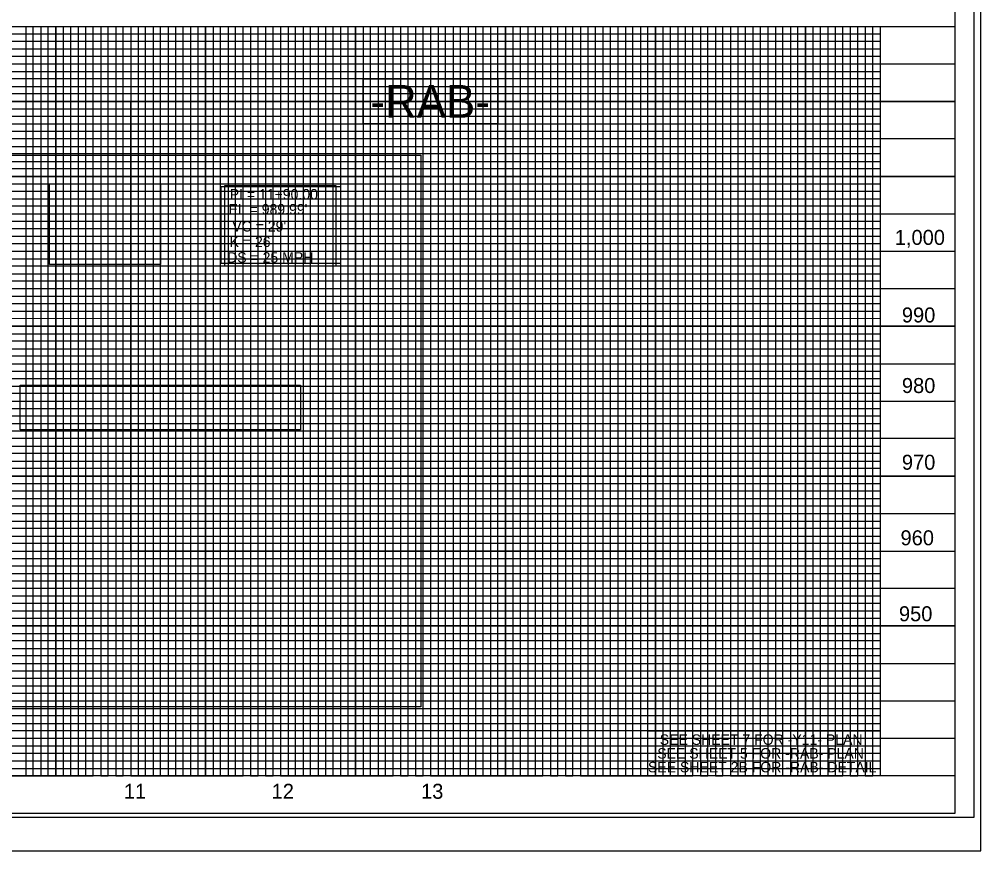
# Model space of a CAD drawing. Extents: x 1628636 to 1631253, y 896159 to 897520.
# Drawn here: x 1630102 to 1630743, y 896159 to 896714 of the extents above; entities that cross this region are included whole.
import ezdxf

# ---------------------------------------------------------------- set-up
doc = ezdxf.new("R2010")
doc.units = 0
for name, color, linetype in [('Prop DSN Text', 7, 'Continuous'), ('Prop PHM Black Shape', 7, 'Continuous'), ('Prop Vertical Profile Curve Label', 7, 'Continuous'), ('Prop VPI Label', 7, 'Continuous'), ('Scratch_Level_6', 7, 'Continuous'), ('Sheet Cutting Line CELL', 7, 'Continuous'), ('Sheet DOT Grid CELL', 7, 'Continuous'), ('Sheet Layout Profile Border Port 2', 7, 'Continuous'), ('Sheet Plot Border Inside CELL', 7, 'Continuous'), ('Sheet Plot Border Outside CELL', 7, 'Continuous'), ('Sheet Profile CELL', 7, 'Continuous'), ('Sheet Profile Grid Major CELL', 7, 'Continuous'), ('Sheet Profile Grid Middle CELL', 7, 'Continuous'), ('Sheet Profile Grid Minor CELL', 7, 'Continuous')]:
    doc.layers.add(name, color=color, linetype=linetype)

msp = doc.modelspace()

# ---------------------------------------------------------------- linework, layer by layer
at = {"layer": 'Prop PHM Black Shape'}
for points in [[(1630331.5, 896673.9), (1630421.5, 896673.9), (1630421.5, 896643.9), (1630331.5, 896643.9)], [(1630122.44, 896603.99), (1630196.49, 896603.99), (1630196.49, 896550.11), (1630122.44, 896550.11)], [(1630236.81, 896602.21), (1630316.54, 896602.21), (1630316.54, 896550.85), (1630236.81, 896550.85)], [(1630239.35, 896602.77), (1630313.4, 896602.77), (1630313.4, 896548.89), (1630239.35, 896548.89)], [(1630102.84, 896469.52), (1630289.81, 896469.52), (1630289.81, 896439.73), (1630102.84, 896439.73)], [(1630521.5, 896238.9), (1630676.5, 896238.9), (1630676.5, 896208.9), (1630521.5, 896208.9)]]:
    msp.add_lwpolyline(points, close=True, dxfattribs=at)
at = {"layer": 'Scratch_Level_6'}
for points in [[(1630176.5, 896658.9), (1630576.5, 896658.9), (1630576.5, 896358.9), (1630176.5, 896358.9)], [(1630068.19, 896623), (1630370.03, 896623), (1630370.03, 896254.89), (1630068.19, 896254.89)]]:
    msp.add_lwpolyline(points, close=True, dxfattribs=at)
at = {"layer": 'Sheet Cutting Line CELL'}
msp.add_line((1629059.5, 896158.9), (1630743.5, 896158.9), dxfattribs=at)
at = {"layer": 'Sheet DOT Grid CELL'}
for p, q in [((1629226.5, 896708.9), (1630726.39, 896708.9)), ((1630126.5, 896708.9), (1630126.5, 896208.9)), ((1630176.5, 896708.9), (1630176.5, 896208.9)), ((1630226.5, 896708.9), (1630226.5, 896208.9)), ((1630276.5, 896708.9), (1630276.5, 896208.9)), ((1630326.5, 896708.9), (1630326.5, 896208.9)), ((1630376.5, 896708.9), (1630376.5, 896208.9)), ((1630426.5, 896708.9), (1630426.5, 896208.9)), ((1630476.5, 896708.9), (1630476.5, 896208.9)), ((1630526.5, 896708.9), (1630526.5, 896208.9)), ((1630576.5, 896708.9), (1630576.5, 896208.9)), ((1630626.5, 896708.9), (1630626.5, 896208.9)), ((1630676.5, 896708.9), (1630676.5, 896208.9)), ((1629226.5, 896658.9), (1630726.39, 896658.9)), ((1629226.5, 896608.9), (1630726.39, 896608.9)), ((1629226.5, 896558.9), (1630726.39, 896558.9)), ((1629226.5, 896508.9), (1630726.39, 896508.9)), ((1629226.5, 896458.9), (1630726.39, 896458.9)), ((1629226.5, 896408.9), (1630726.39, 896408.9)), ((1629226.5, 896358.9), (1630726.39, 896358.9)), ((1629226.5, 896308.9), (1630726.39, 896308.9)), ((1629226.5, 896258.9), (1630726.39, 896258.9))]:
    msp.add_line(p, q, dxfattribs=at)
at = {"layer": 'Sheet Layout Profile Border Port 2'}
msp.add_lwpolyline([(1629276.5, 896708.9), (1630676.5, 896708.9), (1630676.5, 896208.9), (1629276.5, 896208.9)], close=True, dxfattribs=at)
at = {"layer": 'Sheet Plot Border Inside CELL'}
msp.add_lwpolyline([(1629072.5, 896181.35), (1630739, 896181.35), (1630739, 897236.45), (1629072.5, 897236.45)], close=True, dxfattribs=at)
at = {"layer": 'Sheet Plot Border Outside CELL'}
msp.add_lwpolyline([(1629059.5, 896158.9), (1630743.5, 896158.9), (1630743.5, 897258.9), (1629059.5, 897258.9)], close=True, dxfattribs=at)
at = {"layer": 'Sheet Profile CELL'}
for p, q in [((1629226.5, 896708.9), (1630726.5, 896708.9)), ((1630726.5, 896208.9), (1629226.5, 896208.9)), ((1629226.5, 896183.9), (1630726.5, 896183.9))]:
    msp.add_line(p, q, dxfattribs=at)
msp.add_lwpolyline([(1630726.5, 897233.9), (1629226.5, 897233.9), (1629226.5, 896183.9), (1630726.5, 896183.9)], close=True, dxfattribs=at)
at = {"layer": 'Sheet Profile Grid Major CELL'}
for p, q in [((1630126.5, 896708.9), (1630176.5, 896708.9)), ((1630226.5, 896708.9), (1630276.5, 896708.9)), ((1630326.5, 896708.9), (1630376.5, 896708.9)), ((1630426.5, 896708.9), (1630476.5, 896708.9)), ((1630526.5, 896708.9), (1630576.5, 896708.9)), ((1630626.5, 896708.9), (1630676.5, 896708.9)), ((1630626.5, 896208.9), (1630626.5, 896208.9))]:
    msp.add_line(p, q, dxfattribs=at)
for points in [[(1630076.5, 896208.9), (1630126.5, 896208.9), (1630126.5, 896708.9), (1630176.5, 896708.9), (1630176.5, 896208.9), (1630226.5, 896208.9), (1630226.5, 896708.9), (1630276.5, 896708.9), (1630276.5, 896208.9), (1630326.5, 896208.9), (1630326.5, 896708.9), (1630376.5, 896708.9), (1630376.5, 896208.9), (1630426.5, 896208.9), (1630426.5, 896708.9), (1630476.5, 896708.9), (1630476.5, 896208.9), (1630526.5, 896208.9), (1630526.5, 896708.9), (1630576.5, 896708.9), (1630576.5, 896208.9), (1630626.5, 896208.9), (1630626.5, 896208.9), (1630626.5, 896708.9), (1630676.5, 896708.9), (1630676.5, 896208.9)], [(1630726.5, 896658.9), (1629226.5, 896658.9)], [(1630726.5, 896608.9), (1629226.5, 896608.9), (1629226.5, 896558.9), (1630726.5, 896558.9)], [(1630726.5, 896508.9), (1629226.5, 896508.9), (1629226.5, 896458.9), (1630726.5, 896458.9)], [(1630726.5, 896408.9), (1629226.5, 896408.9), (1629226.5, 896358.9), (1630726.5, 896358.9)], [(1630726.5, 896308.9), (1629226.5, 896308.9), (1629226.5, 896308.9), (1629226.5, 896258.9), (1630726.5, 896258.9)], [(1630726.5, 896208.9), (1629226.5, 896208.9)]]:
    msp.add_lwpolyline(points, dxfattribs=at)
at = {"layer": 'Sheet Profile Grid Middle CELL'}
for points in [[(1630101.5, 896208.9), (1630151.5, 896208.9), (1630151.5, 896708.9), (1630201.5, 896708.9), (1630201.5, 896208.9), (1630251.5, 896208.9), (1630251.5, 896708.9), (1630301.5, 896708.9), (1630301.5, 896208.9), (1630351.5, 896208.9), (1630351.5, 896708.9), (1630401.5, 896708.9), (1630401.5, 896208.9), (1630451.5, 896208.9), (1630451.5, 896708.9), (1630501.5, 896708.9), (1630501.5, 896208.9), (1630551.5, 896208.9), (1630551.5, 896708.9), (1630601.5, 896708.9), (1630601.5, 896208.9), (1630651.5, 896208.9), (1630651.5, 896708.9)], [(1629226.5, 896683.9), (1630726.5, 896683.9)], [(1630726.5, 896633.9), (1629226.5, 896633.9), (1629226.5, 896583.9), (1630726.5, 896583.9)], [(1630726.5, 896533.9), (1629226.5, 896533.9), (1629226.5, 896483.9), (1630726.5, 896483.9)], [(1630726.5, 896433.9), (1629226.5, 896433.9), (1629226.5, 896383.9), (1630726.5, 896383.9)], [(1630726.5, 896333.9), (1629226.5, 896333.9), (1629226.5, 896283.9), (1630726.5, 896283.9)], [(1630726.5, 896233.9), (1629226.5, 896233.9)]]:
    msp.add_lwpolyline(points, dxfattribs=at)
at = {"layer": 'Sheet Profile Grid Minor CELL'}
for p, q in [((1629276.5, 896703.9), (1630676.5, 896703.9)), ((1630676.5, 896698.9), (1629276.5, 896698.9)), ((1629276.5, 896693.9), (1630676.5, 896693.9)), ((1630676.5, 896688.9), (1629276.5, 896688.9)), ((1629276.5, 896678.9), (1630676.5, 896678.9)), ((1630676.5, 896673.9), (1629276.5, 896673.9)), ((1629276.5, 896668.9), (1630676.5, 896668.9)), ((1630676.5, 896663.9), (1629276.5, 896663.9)), ((1629276.5, 896653.9), (1630676.5, 896653.9)), ((1630676.5, 896648.9), (1629276.5, 896648.9)), ((1629276.5, 896643.9), (1630676.5, 896643.9)), ((1630676.5, 896638.9), (1629276.5, 896638.9)), ((1629276.5, 896628.9), (1630676.5, 896628.9)), ((1630676.5, 896623.9), (1629276.5, 896623.9)), ((1629276.5, 896618.9), (1630676.5, 896618.9)), ((1630676.5, 896613.9), (1629276.5, 896613.9)), ((1629276.5, 896603.9), (1630676.5, 896603.9)), ((1630676.5, 896598.9), (1629276.5, 896598.9)), ((1629276.5, 896593.9), (1630676.5, 896593.9)), ((1630676.5, 896588.9), (1629276.5, 896588.9)), ((1629276.5, 896578.9), (1630676.5, 896578.9)), ((1630676.5, 896573.9), (1629276.5, 896573.9)), ((1629276.5, 896568.9), (1630676.5, 896568.9)), ((1630676.5, 896563.9), (1629276.5, 896563.9)), ((1629276.5, 896553.9), (1630676.5, 896553.9)), ((1630676.5, 896548.9), (1629276.5, 896548.9)), ((1629276.5, 896543.9), (1630676.5, 896543.9)), ((1630676.5, 896538.9), (1629276.5, 896538.9)), ((1629276.5, 896528.9), (1630676.5, 896528.9)), ((1630676.5, 896523.9), (1629276.5, 896523.9)), ((1629276.5, 896518.9), (1630676.5, 896518.9)), ((1630676.5, 896513.9), (1629276.5, 896514.05)), ((1629276.5, 896503.9), (1630676.5, 896503.9)), ((1630676.5, 896498.9), (1629276.5, 896498.9)), ((1629276.5, 896493.9), (1630676.5, 896493.9)), ((1630676.5, 896488.9), (1629276.5, 896488.9)), ((1629276.5, 896478.9), (1630676.5, 896478.9)), ((1630676.5, 896473.9), (1629276.5, 896473.9)), ((1629276.5, 896468.9), (1630676.5, 896468.9)), ((1630676.5, 896463.9), (1629276.5, 896463.9)), ((1629276.5, 896453.9), (1630676.5, 896453.9)), ((1630676.5, 896448.9), (1629276.5, 896448.9)), ((1629276.5, 896443.9), (1630676.5, 896443.9)), ((1630676.5, 896438.9), (1629276.5, 896438.9)), ((1629276.5, 896428.9), (1630676.5, 896428.9)), ((1630676.5, 896423.9), (1629276.5, 896423.9)), ((1629276.5, 896418.9), (1630676.5, 896418.9)), ((1630676.5, 896413.9), (1629276.5, 896413.9)), ((1629276.5, 896403.9), (1630676.5, 896403.9)), ((1630676.5, 896398.9), (1629276.5, 896398.9)), ((1629276.5, 896393.9), (1630676.5, 896393.9)), ((1630676.5, 896388.9), (1629276.5, 896388.9)), ((1629276.5, 896378.9), (1630676.5, 896378.9)), ((1630676.5, 896373.9), (1629276.5, 896373.9)), ((1629276.5, 896368.9), (1630676.5, 896368.9)), ((1630676.5, 896363.9), (1629276.5, 896363.9)), ((1629276.5, 896353.9), (1630676.5, 896353.9)), ((1630676.5, 896348.9), (1629276.5, 896348.9)), ((1629276.5, 896343.9), (1630676.5, 896343.9)), ((1630676.5, 896338.9), (1629276.5, 896338.9)), ((1629276.5, 896328.9), (1630676.5, 896328.9)), ((1630676.5, 896323.9), (1629276.5, 896323.9)), ((1629276.5, 896318.9), (1630676.5, 896318.9)), ((1630676.5, 896313.9), (1629276.5, 896313.9)), ((1629276.5, 896303.9), (1630676.5, 896303.9)), ((1630676.5, 896298.9), (1629276.5, 896298.9)), ((1629276.5, 896293.9), (1630676.5, 896293.9)), ((1630676.5, 896288.9), (1629276.5, 896288.9)), ((1629276.5, 896278.9), (1630676.5, 896278.9)), ((1630676.5, 896273.9), (1629276.5, 896273.9)), ((1629276.5, 896268.9), (1630676.5, 896268.9)), ((1630676.5, 896263.9), (1629276.5, 896263.9)), ((1629276.5, 896253.9), (1630676.5, 896253.9)), ((1630676.5, 896248.9), (1629276.5, 896248.9)), ((1629276.5, 896243.9), (1630676.5, 896243.9)), ((1630676.5, 896238.9), (1629276.5, 896238.9)), ((1629276.5, 896228.9), (1630676.5, 896228.9)), ((1630676.5, 896223.9), (1629276.5, 896223.9)), ((1629276.5, 896218.9), (1630676.5, 896218.9)), ((1629276.5, 896213.9), (1630676.5, 896213.9)), ((1630676.5, 896213.9), (1630676.5, 896213.9))]:
    msp.add_line(p, q, dxfattribs=at)
for points in [[(1630096.5, 896708.9), (1630106.5, 896708.9), (1630106.5, 896208.9), (1630111.5, 896208.9)], [(1630111.5, 896208.9), (1630111.5, 896708.9), (1630116.5, 896708.9), (1630116.5, 896208.9), (1630121.5, 896208.9), (1630121.5, 896708.9), (1630131.5, 896708.9), (1630131.5, 896208.9), (1630136.5, 896208.9), (1630136.5, 896708.9), (1630141.5, 896708.9), (1630141.5, 896208.9), (1630146.5, 896208.9), (1630146.5, 896708.9), (1630156.5, 896708.9), (1630156.5, 896208.9), (1630161.5, 896208.9), (1630161.5, 896708.9), (1630166.5, 896708.9), (1630166.5, 896208.9), (1630171.5, 896208.9), (1630171.5, 896708.9), (1630181.5, 896708.9), (1630181.5, 896208.9), (1630186.5, 896208.9), (1630186.5, 896708.9), (1630191.5, 896708.9), (1630191.5, 896208.9), (1630196.5, 896208.9), (1630196.5, 896708.9), (1630206.5, 896708.9), (1630206.5, 896208.9), (1630211.5, 896208.9), (1630211.5, 896708.9), (1630216.5, 896708.9), (1630216.5, 896208.9), (1630221.5, 896208.9), (1630221.5, 896708.9), (1630231.5, 896708.9), (1630231.5, 896208.9), (1630236.5, 896208.9), (1630236.5, 896708.9), (1630241.5, 896708.9), (1630241.5, 896208.9), (1630246.5, 896208.9), (1630246.5, 896708.9), (1630256.5, 896708.9), (1630256.5, 896208.9), (1630261.5, 896208.9), (1630261.5, 896708.9), (1630266.5, 896708.9), (1630266.5, 896208.9), (1630271.5, 896208.9), (1630271.5, 896708.9), (1630281.5, 896708.9), (1630281.5, 896208.9), (1630286.5, 896208.9), (1630286.5, 896708.9), (1630291.5, 896708.9), (1630291.5, 896208.9), (1630296.5, 896208.9), (1630296.5, 896708.9), (1630306.5, 896708.9), (1630306.5, 896208.9), (1630311.5, 896208.9), (1630311.5, 896708.9), (1630316.5, 896708.9), (1630316.5, 896208.9), (1630321.5, 896208.9), (1630321.5, 896708.9), (1630331.5, 896708.9), (1630331.5, 896208.9), (1630336.5, 896208.9), (1630336.5, 896708.9), (1630341.5, 896708.9), (1630341.5, 896208.9), (1630346.5, 896208.9), (1630346.5, 896708.9), (1630356.5, 896708.9), (1630356.5, 896208.9), (1630361.5, 896208.9), (1630361.5, 896708.9), (1630366.5, 896708.9), (1630366.5, 896208.9), (1630371.5, 896208.9), (1630371.5, 896708.9), (1630381.5, 896708.9), (1630381.5, 896208.9), (1630386.5, 896208.9), (1630386.5, 896708.9), (1630391.5, 896708.9), (1630391.5, 896208.9), (1630396.5, 896208.9), (1630396.5, 896708.9), (1630406.5, 896708.9), (1630406.5, 896208.9), (1630411.5, 896208.9), (1630411.5, 896708.9), (1630416.5, 896708.9), (1630416.5, 896208.9)], [(1630416.5, 896208.9), (1630421.5, 896208.9), (1630421.5, 896708.9), (1630431.5, 896708.9), (1630431.5, 896208.9), (1630436.5, 896208.9), (1630436.5, 896708.9), (1630441.5, 896708.9), (1630441.5, 896208.9), (1630446.5, 896208.9), (1630446.5, 896708.9), (1630456.5, 896708.9), (1630456.5, 896208.9), (1630461.5, 896208.9), (1630461.5, 896708.9), (1630466.5, 896708.9), (1630466.5, 896208.9), (1630471.5, 896208.9), (1630471.5, 896708.9), (1630481.5, 896708.9), (1630481.5, 896208.9), (1630486.5, 896208.9), (1630486.5, 896708.9), (1630491.5, 896708.9), (1630491.5, 896208.9), (1630496.5, 896208.9), (1630496.5, 896708.9), (1630506.5, 896708.9), (1630506.5, 896208.9), (1630511.5, 896208.9), (1630511.5, 896708.9), (1630516.5, 896708.9), (1630516.5, 896208.9), (1630521.5, 896208.9), (1630521.5, 896708.9), (1630531.5, 896708.9), (1630531.5, 896208.9), (1630536.5, 896208.9), (1630536.5, 896708.9), (1630541.5, 896708.9), (1630541.5, 896208.9), (1630546.5, 896208.9), (1630546.5, 896708.9), (1630556.5, 896708.9), (1630556.5, 896208.9), (1630561.5, 896208.9), (1630561.5, 896708.9), (1630566.5, 896708.9), (1630566.5, 896208.9), (1630571.5, 896208.9), (1630571.5, 896708.9), (1630581.5, 896708.9), (1630581.5, 896208.9), (1630586.5, 896208.9), (1630586.5, 896708.9), (1630591.5, 896708.9), (1630591.5, 896208.9), (1630596.5, 896208.9), (1630596.5, 896708.9), (1630606.5, 896708.9), (1630606.5, 896208.9), (1630611.5, 896208.9), (1630611.5, 896708.9), (1630616.5, 896708.9), (1630616.5, 896208.9), (1630621.5, 896208.9), (1630621.5, 896708.9), (1630631.5, 896708.9), (1630631.5, 896208.9), (1630636.5, 896208.9), (1630636.5, 896708.9), (1630641.5, 896708.9), (1630641.5, 896208.9), (1630646.5, 896208.9), (1630646.5, 896708.9), (1630656.5, 896708.9), (1630656.5, 896208.9), (1630661.5, 896208.9), (1630661.5, 896708.9), (1630666.5, 896708.9), (1630666.5, 896208.9), (1630671.5, 896208.9), (1630671.5, 896708.9), (1630676.5, 896708.9)]]:
    msp.add_lwpolyline(points, dxfattribs=at)

# ---------------------------------------------------------------- texts
at = {"layer": 'Prop DSN Text'}
for s, height, p in [('-RAB-', 21.875, (1630336.43, 896647.96)), ('1,000', 10, (1630686.15, 896563.17)), ('990', 10, (1630690.89, 896511.41)), ('980', 10, (1630690.89, 896464.33)), ('970', 10, (1630690.89, 896413.14)), ('960', 10, (1630689.97, 896362.72)), ('950', 10, (1630688.93, 896312.05)), ('11', 10, (1630171.94, 896193.58)), ('12', 10, (1630270.51, 896193.58)), ('13', 10, (1630370.18, 896193.58))]:
    msp.add_text(s, height=height, dxfattribs=at).set_placement(p)
at = {"layer": 'Prop PHM Black Shape'}
for s, p in [('SEE SHEET 7 FOR -Y11- PLAN', (1630529.39, 896229.57)), ('SEE SHEET 5 FOR -RAB- PLAN', (1630527.72, 896220.4)), ('SEE SHEET 2B FOR -RAB- DETAIL', (1630521.54, 896211.22))]:
    msp.add_text(s, height=7, dxfattribs=at).set_placement(p)
at = {"layer": 'Prop Vertical Profile Curve Label'}
msp.add_text("VC = 29'", height=7, dxfattribs=at).set_placement((1630244.29, 896572.06))
at = {"layer": 'Prop VPI Label'}
for s, p in [('PI = 11+90.00', (1630242.56, 896593.44)), ("EL = 989.99'", (1630241.8, 896583.43)), ('K = 26', (1630242.49, 896561.77)), ('DS = 25 MPH', (1630240.84, 896551.28))]:
    msp.add_text(s, height=7, dxfattribs=at).set_placement(p)

doc.saveas('drawing.dxf')
